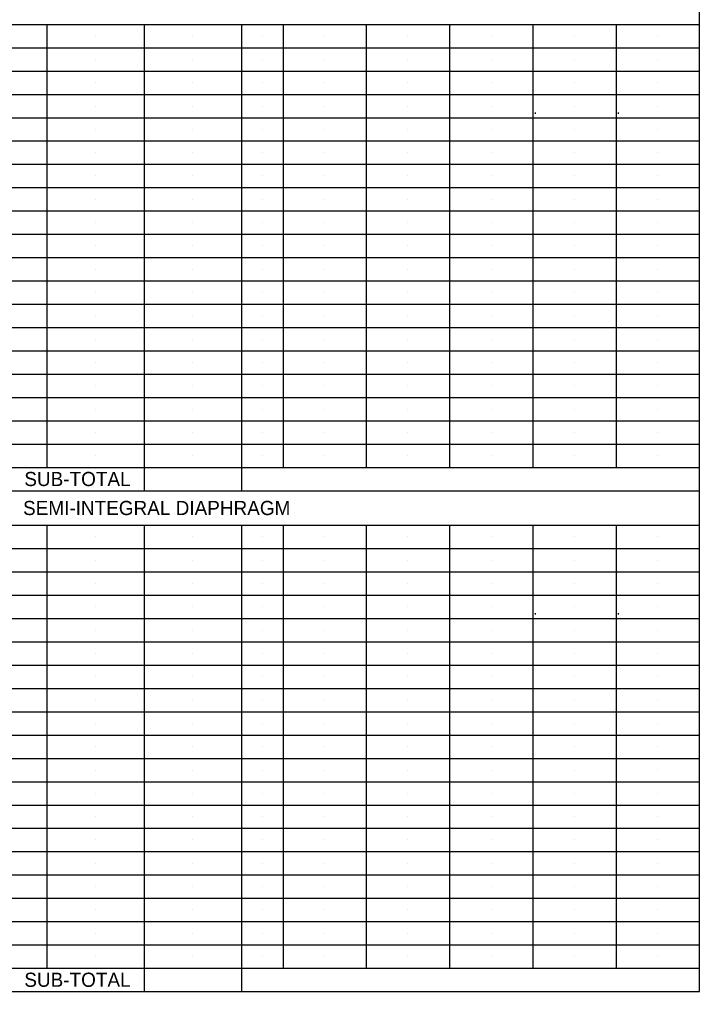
# Model space of a CAD drawing. Extents: x -18.5 to 33.3, y 0.6 to 37.5.
# Drawn here: x -13.03 to -4.86, y 1.28 to 12.95 of the extents above; entities that cross this region are included whole.
import ezdxf

# ---------------------------------------------------------------- set-up
doc = ezdxf.new("R2010")
doc.units = 0
doc.layers.add('BR_X_Beam_Centerline', color=7, linetype='Continuous')

msp = doc.modelspace()

# ---------------------------------------------------------------- linework, layer by layer
at = {"layer": 'BR_X_Beam_Centerline'}
for p, q in [((-4.862, 7.291), (-4.862, 20.715)), ((-18.496, 12.891), (-4.862, 12.891)), ((-12.696, 12.891), (-12.696, 7.571)), ((-11.529, 12.891), (-11.529, 7.291)), ((-10.362, 12.891), (-10.362, 7.291)), ((-9.862, 12.891), (-9.862, 7.571)), ((-8.862, 12.891), (-8.862, 7.571)), ((-7.862, 12.891), (-7.862, 7.571)), ((-6.862, 12.891), (-6.862, 7.571)), ((-5.862, 12.891), (-5.862, 7.571)), ((-5.862, 12.891), (-5.862, 7.571)), ((-12.112, 12.751), (-12.112, 12.751)), ((-10.946, 12.751), (-10.946, 12.751)), ((-10.112, 12.751), (-10.112, 12.751)), ((-9.362, 12.751), (-9.362, 12.751)), ((-8.362, 12.751), (-8.362, 12.751)), ((-7.362, 12.751), (-7.362, 12.751)), ((-6.362, 12.751), (-6.362, 12.751)), ((-5.362, 12.751), (-5.362, 12.751)), ((-18.496, 12.611), (-4.862, 12.611)), ((-12.112, 12.471), (-12.112, 12.471)), ((-10.946, 12.471), (-10.946, 12.471)), ((-10.112, 12.471), (-10.112, 12.471)), ((-9.362, 12.471), (-9.362, 12.471)), ((-8.362, 12.471), (-8.362, 12.471)), ((-7.362, 12.471), (-7.362, 12.471)), ((-6.362, 12.471), (-6.362, 12.471)), ((-5.362, 12.471), (-5.362, 12.471)), ((-18.496, 12.331), (-4.862, 12.331)), ((-12.112, 12.191), (-12.112, 12.191)), ((-10.946, 12.191), (-10.946, 12.191)), ((-10.112, 12.191), (-10.112, 12.191)), ((-9.362, 12.191), (-9.362, 12.191)), ((-8.362, 12.191), (-8.362, 12.191)), ((-7.362, 12.191), (-7.362, 12.191)), ((-6.362, 12.191), (-6.362, 12.191)), ((-5.362, 12.191), (-5.362, 12.191)), ((-18.496, 12.051), (-4.862, 12.051)), ((-12.112, 11.911), (-12.112, 11.911)), ((-10.946, 11.911), (-10.946, 11.911)), ((-10.112, 11.911), (-10.112, 11.911)), ((-9.362, 11.911), (-9.362, 11.911)), ((-8.362, 11.911), (-8.362, 11.911)), ((-7.362, 11.911), (-7.362, 11.911)), ((-6.362, 11.911), (-6.362, 11.911)), ((-5.362, 11.911), (-5.362, 11.911)), ((-6.832, 11.819), (-6.832, 11.835)), ((-5.837, 11.819), (-5.837, 11.835)), ((-18.496, 11.771), (-4.862, 11.771)), ((-12.112, 11.631), (-12.112, 11.631)), ((-10.946, 11.631), (-10.946, 11.631)), ((-10.112, 11.631), (-10.112, 11.631)), ((-9.362, 11.631), (-9.362, 11.631)), ((-8.362, 11.631), (-8.362, 11.631)), ((-7.362, 11.631), (-7.362, 11.631)), ((-6.362, 11.631), (-6.362, 11.631)), ((-5.362, 11.631), (-5.362, 11.631)), ((-18.496, 11.491), (-4.862, 11.491)), ((-12.112, 11.351), (-12.112, 11.351)), ((-10.946, 11.351), (-10.946, 11.351)), ((-10.112, 11.351), (-10.112, 11.351)), ((-9.362, 11.351), (-9.362, 11.351)), ((-8.362, 11.351), (-8.362, 11.351)), ((-7.362, 11.351), (-7.362, 11.351)), ((-6.362, 11.351), (-6.362, 11.351)), ((-5.362, 11.351), (-5.362, 11.351)), ((-18.496, 11.211), (-4.862, 11.211)), ((-12.112, 11.071), (-12.112, 11.071)), ((-10.946, 11.071), (-10.946, 11.071)), ((-10.112, 11.071), (-10.112, 11.071)), ((-9.362, 11.071), (-9.362, 11.071)), ((-8.362, 11.071), (-8.362, 11.071)), ((-7.362, 11.071), (-7.362, 11.071)), ((-6.362, 11.071), (-6.362, 11.071)), ((-5.362, 11.071), (-5.362, 11.071)), ((-18.496, 10.931), (-4.862, 10.931)), ((-12.112, 10.791), (-12.112, 10.791)), ((-10.946, 10.791), (-10.946, 10.791)), ((-10.112, 10.791), (-10.112, 10.791)), ((-9.362, 10.791), (-9.362, 10.791)), ((-8.362, 10.791), (-8.362, 10.791)), ((-7.362, 10.791), (-7.362, 10.791)), ((-6.362, 10.791), (-6.362, 10.791)), ((-5.362, 10.791), (-5.362, 10.791)), ((-18.496, 10.651), (-4.862, 10.651)), ((-12.112, 10.511), (-12.112, 10.511)), ((-10.946, 10.511), (-10.946, 10.511)), ((-10.112, 10.511), (-10.112, 10.511)), ((-9.362, 10.511), (-9.362, 10.511)), ((-8.362, 10.511), (-8.362, 10.511)), ((-7.362, 10.511), (-7.362, 10.511)), ((-6.362, 10.511), (-6.362, 10.511)), ((-5.362, 10.511), (-5.362, 10.511)), ((-18.496, 10.371), (-4.862, 10.371)), ((-12.112, 10.231), (-12.112, 10.231)), ((-10.946, 10.231), (-10.946, 10.231)), ((-10.112, 10.231), (-10.112, 10.231)), ((-9.362, 10.231), (-9.362, 10.231)), ((-8.362, 10.231), (-8.362, 10.231)), ((-7.362, 10.231), (-7.362, 10.231)), ((-6.362, 10.231), (-6.362, 10.231)), ((-5.362, 10.231), (-5.362, 10.231)), ((-18.496, 10.091), (-4.862, 10.091)), ((-12.112, 9.951), (-12.112, 9.951)), ((-10.946, 9.951), (-10.946, 9.951)), ((-10.112, 9.951), (-10.112, 9.951)), ((-9.362, 9.951), (-9.362, 9.951)), ((-8.362, 9.951), (-8.362, 9.951)), ((-7.362, 9.951), (-7.362, 9.951)), ((-6.362, 9.951), (-6.362, 9.951)), ((-5.362, 9.951), (-5.362, 9.951)), ((-18.496, 9.811), (-4.862, 9.811)), ((-12.112, 9.671), (-12.112, 9.671)), ((-10.946, 9.671), (-10.946, 9.671)), ((-10.112, 9.671), (-10.112, 9.671)), ((-9.362, 9.671), (-9.362, 9.671)), ((-8.362, 9.671), (-8.362, 9.671)), ((-7.362, 9.671), (-7.362, 9.671)), ((-6.362, 9.671), (-6.362, 9.671)), ((-5.362, 9.671), (-5.362, 9.671)), ((-18.496, 9.531), (-4.862, 9.531)), ((-12.112, 9.391), (-12.112, 9.391)), ((-10.946, 9.391), (-10.946, 9.391)), ((-10.112, 9.391), (-10.112, 9.391)), ((-9.362, 9.391), (-9.362, 9.391)), ((-8.362, 9.391), (-8.362, 9.391)), ((-7.362, 9.391), (-7.362, 9.391)), ((-6.362, 9.391), (-6.362, 9.391)), ((-5.362, 9.391), (-5.362, 9.391)), ((-18.496, 9.251), (-4.862, 9.251)), ((-12.112, 9.111), (-12.112, 9.111)), ((-10.946, 9.111), (-10.946, 9.111)), ((-10.112, 9.111), (-10.112, 9.111)), ((-9.362, 9.111), (-9.362, 9.111)), ((-8.362, 9.111), (-8.362, 9.111)), ((-7.362, 9.111), (-7.362, 9.111)), ((-6.362, 9.111), (-6.362, 9.111)), ((-5.362, 9.111), (-5.362, 9.111)), ((-18.496, 8.971), (-4.862, 8.971)), ((-12.112, 8.831), (-12.112, 8.831)), ((-10.946, 8.831), (-10.946, 8.831)), ((-10.112, 8.831), (-10.112, 8.831)), ((-9.362, 8.831), (-9.362, 8.831)), ((-8.362, 8.831), (-8.362, 8.831)), ((-7.362, 8.831), (-7.362, 8.831)), ((-6.362, 8.831), (-6.362, 8.831)), ((-5.362, 8.831), (-5.362, 8.831)), ((-18.496, 8.691), (-4.862, 8.691)), ((-12.112, 8.551), (-12.112, 8.551)), ((-10.946, 8.551), (-10.946, 8.551)), ((-10.112, 8.551), (-10.112, 8.551)), ((-9.362, 8.551), (-9.362, 8.551)), ((-8.362, 8.551), (-8.362, 8.551)), ((-7.362, 8.551), (-7.362, 8.551)), ((-6.362, 8.551), (-6.362, 8.551)), ((-5.362, 8.551), (-5.362, 8.551)), ((-18.496, 8.411), (-4.862, 8.411)), ((-12.112, 8.271), (-12.112, 8.271)), ((-10.946, 8.271), (-10.946, 8.271)), ((-10.112, 8.271), (-10.112, 8.271)), ((-9.362, 8.271), (-9.362, 8.271)), ((-8.362, 8.271), (-8.362, 8.271)), ((-7.362, 8.271), (-7.362, 8.271)), ((-6.362, 8.271), (-6.362, 8.271)), ((-5.362, 8.271), (-5.362, 8.271)), ((-18.496, 8.131), (-4.862, 8.131)), ((-12.112, 7.991), (-12.112, 7.991)), ((-10.946, 7.991), (-10.946, 7.991)), ((-10.112, 7.991), (-10.112, 7.991)), ((-9.362, 7.991), (-9.362, 7.991)), ((-8.362, 7.991), (-8.362, 7.991)), ((-7.362, 7.991), (-7.362, 7.991)), ((-6.362, 7.991), (-6.362, 7.991)), ((-5.362, 7.991), (-5.362, 7.991)), ((-18.496, 7.851), (-4.862, 7.851)), ((-12.112, 7.711), (-12.112, 7.711)), ((-10.946, 7.711), (-10.946, 7.711)), ((-10.112, 7.711), (-10.112, 7.711)), ((-9.362, 7.711), (-9.362, 7.711)), ((-8.362, 7.711), (-8.362, 7.711)), ((-7.362, 7.711), (-7.362, 7.711)), ((-6.362, 7.711), (-6.362, 7.711)), ((-5.362, 7.711), (-5.362, 7.711)), ((-18.496, 7.571), (-4.862, 7.571)), ((-18.496, 7.291), (-4.862, 7.291)), ((-4.862, 1.279), (-4.862, 7.291)), ((-11.279, 7.085), (-11.279, 7.085)), ((-18.496, 6.879), (-4.862, 6.879)), ((-12.696, 6.879), (-12.696, 1.559)), ((-11.529, 6.879), (-11.529, 1.279)), ((-10.362, 6.879), (-10.362, 1.279)), ((-9.862, 6.879), (-9.862, 1.559)), ((-8.862, 6.879), (-8.862, 1.559)), ((-7.862, 6.879), (-7.862, 1.559)), ((-6.862, 6.879), (-6.862, 1.559)), ((-5.862, 6.879), (-5.862, 1.559)), ((-5.862, 6.879), (-5.862, 1.559)), ((-12.112, 6.739), (-12.112, 6.739)), ((-10.946, 6.739), (-10.946, 6.739)), ((-10.112, 6.739), (-10.112, 6.739)), ((-9.362, 6.739), (-9.362, 6.739)), ((-8.362, 6.739), (-8.362, 6.739)), ((-7.362, 6.739), (-7.362, 6.739)), ((-6.362, 6.739), (-6.362, 6.739)), ((-5.362, 6.74), (-5.362, 6.74)), ((-18.496, 6.599), (-4.862, 6.599)), ((-12.112, 6.459), (-12.112, 6.459)), ((-10.946, 6.459), (-10.946, 6.459)), ((-10.112, 6.459), (-10.112, 6.459)), ((-9.362, 6.459), (-9.362, 6.459)), ((-8.362, 6.459), (-8.362, 6.459)), ((-7.362, 6.459), (-7.362, 6.459)), ((-6.362, 6.459), (-6.362, 6.459)), ((-5.362, 6.46), (-5.362, 6.46)), ((-18.496, 6.319), (-4.862, 6.319)), ((-12.112, 6.179), (-12.112, 6.179)), ((-10.946, 6.179), (-10.946, 6.179)), ((-10.112, 6.179), (-10.112, 6.179)), ((-9.362, 6.179), (-9.362, 6.179)), ((-8.362, 6.179), (-8.362, 6.179)), ((-7.362, 6.179), (-7.362, 6.179)), ((-6.362, 6.179), (-6.362, 6.179)), ((-5.362, 6.18), (-5.362, 6.18)), ((-18.496, 6.039), (-4.862, 6.039)), ((-12.112, 5.899), (-12.112, 5.899)), ((-10.946, 5.899), (-10.946, 5.899)), ((-10.112, 5.899), (-10.112, 5.899)), ((-9.362, 5.899), (-9.362, 5.899)), ((-8.362, 5.899), (-8.362, 5.899)), ((-7.362, 5.899), (-7.362, 5.899)), ((-6.362, 5.899), (-6.362, 5.899)), ((-5.362, 5.9), (-5.362, 5.9)), ((-18.496, 5.759), (-4.862, 5.759)), ((-6.832, 5.807), (-6.832, 5.823)), ((-5.837, 5.807), (-5.837, 5.823)), ((-12.112, 5.619), (-12.112, 5.619)), ((-10.946, 5.619), (-10.946, 5.619)), ((-10.112, 5.619), (-10.112, 5.619)), ((-9.362, 5.619), (-9.362, 5.619)), ((-8.362, 5.619), (-8.362, 5.619)), ((-7.362, 5.619), (-7.362, 5.619)), ((-6.362, 5.619), (-6.362, 5.619)), ((-5.362, 5.62), (-5.362, 5.62)), ((-18.496, 5.479), (-4.862, 5.479)), ((-12.112, 5.339), (-12.112, 5.339)), ((-10.946, 5.339), (-10.946, 5.339)), ((-10.112, 5.339), (-10.112, 5.339)), ((-9.362, 5.339), (-9.362, 5.339)), ((-8.362, 5.339), (-8.362, 5.339)), ((-7.362, 5.339), (-7.362, 5.339)), ((-6.362, 5.339), (-6.362, 5.339)), ((-5.362, 5.34), (-5.362, 5.34)), ((-18.496, 5.199), (-4.862, 5.199)), ((-12.112, 5.059), (-12.112, 5.059)), ((-10.946, 5.059), (-10.946, 5.059)), ((-10.112, 5.059), (-10.112, 5.059)), ((-9.362, 5.059), (-9.362, 5.059)), ((-8.362, 5.059), (-8.362, 5.059)), ((-7.362, 5.059), (-7.362, 5.059)), ((-6.362, 5.059), (-6.362, 5.059)), ((-5.362, 5.06), (-5.362, 5.06)), ((-18.496, 4.919), (-4.862, 4.919)), ((-12.112, 4.779), (-12.112, 4.779)), ((-10.946, 4.779), (-10.946, 4.779)), ((-10.112, 4.779), (-10.112, 4.779)), ((-9.362, 4.779), (-9.362, 4.779)), ((-8.362, 4.779), (-8.362, 4.779)), ((-7.362, 4.779), (-7.362, 4.779)), ((-6.362, 4.779), (-6.362, 4.779)), ((-5.362, 4.78), (-5.362, 4.78)), ((-18.496, 4.639), (-4.862, 4.639)), ((-12.112, 4.499), (-12.112, 4.499)), ((-10.946, 4.499), (-10.946, 4.499)), ((-10.112, 4.499), (-10.112, 4.499)), ((-9.362, 4.499), (-9.362, 4.499)), ((-8.362, 4.499), (-8.362, 4.499)), ((-7.362, 4.499), (-7.362, 4.499)), ((-6.362, 4.499), (-6.362, 4.499)), ((-5.362, 4.5), (-5.362, 4.5)), ((-18.496, 4.359), (-4.862, 4.359)), ((-12.112, 4.219), (-12.112, 4.219)), ((-10.946, 4.219), (-10.946, 4.219)), ((-10.112, 4.219), (-10.112, 4.219)), ((-9.362, 4.219), (-9.362, 4.219)), ((-8.362, 4.219), (-8.362, 4.219)), ((-7.362, 4.219), (-7.362, 4.219)), ((-6.362, 4.219), (-6.362, 4.219)), ((-5.362, 4.22), (-5.362, 4.22)), ((-18.496, 4.079), (-4.862, 4.079)), ((-12.112, 3.939), (-12.112, 3.939)), ((-10.946, 3.939), (-10.946, 3.939)), ((-10.112, 3.939), (-10.112, 3.939)), ((-9.362, 3.939), (-9.362, 3.939)), ((-8.362, 3.939), (-8.362, 3.939)), ((-7.362, 3.939), (-7.362, 3.939)), ((-6.362, 3.939), (-6.362, 3.939)), ((-5.362, 3.94), (-5.362, 3.94)), ((-18.496, 3.799), (-4.862, 3.799)), ((-12.112, 3.659), (-12.112, 3.659)), ((-10.946, 3.659), (-10.946, 3.659)), ((-10.112, 3.659), (-10.112, 3.659)), ((-9.362, 3.659), (-9.362, 3.659)), ((-8.362, 3.659), (-8.362, 3.659)), ((-7.362, 3.659), (-7.362, 3.659)), ((-6.362, 3.659), (-6.362, 3.659)), ((-5.362, 3.66), (-5.362, 3.66)), ((-18.496, 3.519), (-4.862, 3.519)), ((-12.112, 3.379), (-12.112, 3.379)), ((-10.946, 3.379), (-10.946, 3.379)), ((-10.112, 3.379), (-10.112, 3.379)), ((-9.362, 3.379), (-9.362, 3.379)), ((-8.362, 3.379), (-8.362, 3.379)), ((-7.362, 3.379), (-7.362, 3.379)), ((-6.362, 3.379), (-6.362, 3.379)), ((-5.362, 3.38), (-5.362, 3.38)), ((-18.496, 3.239), (-4.862, 3.239)), ((-12.112, 3.099), (-12.112, 3.099)), ((-10.946, 3.099), (-10.946, 3.099)), ((-10.112, 3.099), (-10.112, 3.099)), ((-9.362, 3.099), (-9.362, 3.099)), ((-8.362, 3.099), (-8.362, 3.099)), ((-7.362, 3.099), (-7.362, 3.099)), ((-6.362, 3.099), (-6.362, 3.099)), ((-5.362, 3.1), (-5.362, 3.1)), ((-18.496, 2.959), (-4.862, 2.959)), ((-12.112, 2.819), (-12.112, 2.819)), ((-10.946, 2.819), (-10.946, 2.819)), ((-10.112, 2.819), (-10.112, 2.819)), ((-9.362, 2.819), (-9.362, 2.819)), ((-8.362, 2.819), (-8.362, 2.819)), ((-7.362, 2.819), (-7.362, 2.819)), ((-6.362, 2.819), (-6.362, 2.819)), ((-5.362, 2.82), (-5.362, 2.82)), ((-18.496, 2.679), (-4.862, 2.679)), ((-12.112, 2.539), (-12.112, 2.539)), ((-10.946, 2.539), (-10.946, 2.539)), ((-10.112, 2.539), (-10.112, 2.539)), ((-9.362, 2.539), (-9.362, 2.539)), ((-8.362, 2.539), (-8.362, 2.539)), ((-7.362, 2.539), (-7.362, 2.539)), ((-6.362, 2.539), (-6.362, 2.539)), ((-5.362, 2.54), (-5.362, 2.54)), ((-18.496, 2.399), (-4.862, 2.399)), ((-12.112, 2.259), (-12.112, 2.259)), ((-10.946, 2.259), (-10.946, 2.259)), ((-10.112, 2.259), (-10.112, 2.259)), ((-9.362, 2.259), (-9.362, 2.259)), ((-8.362, 2.259), (-8.362, 2.259)), ((-7.362, 2.259), (-7.362, 2.259)), ((-6.362, 2.259), (-6.362, 2.259)), ((-5.362, 2.26), (-5.362, 2.26)), ((-18.496, 2.119), (-4.862, 2.119)), ((-12.112, 1.979), (-12.112, 1.979)), ((-10.946, 1.979), (-10.946, 1.979)), ((-10.112, 1.979), (-10.112, 1.979)), ((-9.362, 1.979), (-9.362, 1.979)), ((-8.362, 1.979), (-8.362, 1.979)), ((-7.362, 1.979), (-7.362, 1.979)), ((-6.362, 1.979), (-6.362, 1.979)), ((-5.362, 1.98), (-5.362, 1.98)), ((-18.496, 1.839), (-4.862, 1.839)), ((-12.112, 1.699), (-12.112, 1.699)), ((-10.946, 1.699), (-10.946, 1.699)), ((-10.112, 1.699), (-10.112, 1.699)), ((-9.362, 1.699), (-9.362, 1.699)), ((-8.362, 1.699), (-8.362, 1.699)), ((-7.362, 1.699), (-7.362, 1.699)), ((-6.362, 1.699), (-6.362, 1.699)), ((-5.362, 1.7), (-5.362, 1.7)), ((-18.496, 1.559), (-4.862, 1.559)), ((-18.496, 1.279), (-4.862, 1.279))]:
    msp.add_line(p, q, dxfattribs=at)

# ---------------------------------------------------------------- texts
for s, p in [('SUB-TOTAL', (-12.967, 7.348)), ('SEMI-INTEGRAL DIAPHRAGM', (-12.982, 7)), ('SUB-TOTAL', (-12.967, 1.336))]:
    msp.add_text(s, height=0.17, dxfattribs=at).set_placement(p)

doc.saveas('drawing.dxf')
